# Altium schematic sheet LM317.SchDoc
size B
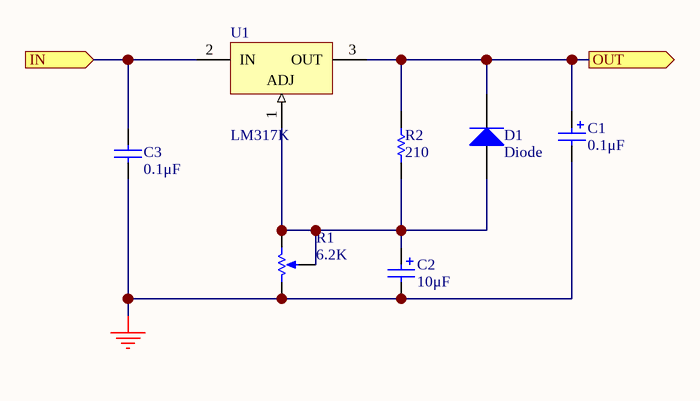
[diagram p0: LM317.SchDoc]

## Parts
C1  0.1μF  [RB7.6-15]
C2  10μF  [RB7.6-15]
C3  0.1μF  [RAD-0.3]
D1  Diode  [DSO-C2/X3.3]
R1  6.2K  [VR5]
R2  210  [AXIAL-0.3]
U1  LM317K  [MBFM-P2/B2.3]

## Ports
IN (in), OUT (out)

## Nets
GND: C1.2 C2.2 C3.1 R1.2(BOT)
IN: C3.2 U1.2(IN) ; port IN
OUT: C1.1 D1.2(K) R2.2 U1.3(OUT) ; port OUT
NetC2_1: C2.1 D1.1(A) R1.1(TOP) R1.3(TAP) R2.1 U1.1(ADJ)

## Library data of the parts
C1 C2 = Cap Pol1: Polarized Capacitor (Radial); Manufacturer: Generic Components; Class I: Passive
C3 = Cap: Capacitor; Manufacturer: Generic Components; Class I: Passive
D1 = Diode: Default Diode; Manufacturer: Generic Components; Class I: Discrete; Class II: Diode - Switching
R1 = RPot1: Potentiometer; Manufacturer: Generic Components; Class I: Passive; Set Position: 0.5
R2 = Res1: Resistor; Manufacturer: Generic Components; Class I: Passive
U1 = LM317K: 1.2V to 37V Voltage Regulator; Manufacturer: ST-Microelectronics; Class I: Power Management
